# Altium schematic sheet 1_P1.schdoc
size 307 x 218 mm; Symbol: Drawing-Symbol_A4; Device: Drawing-Symbol_A4; Company: 嘉立创EDA; Version: V1.0; Page Size: A4; @Project Name: backscatter; @Page Count: 1; @Update Date: 2026-03-28; @Create Date: 2026-03-27; @Schematic Name: Schematic1; @Page No: 1; @Page Name: P1; @Board Name: Board1; @Create Time: 00:06:39; @Update Time: 16:08:41; Title Block Position: 3; Size: A4; Width: 1170; Height: 825; Region Start: 1; X Region Count: 6; Y Region Count: 4; Blade Width: 10
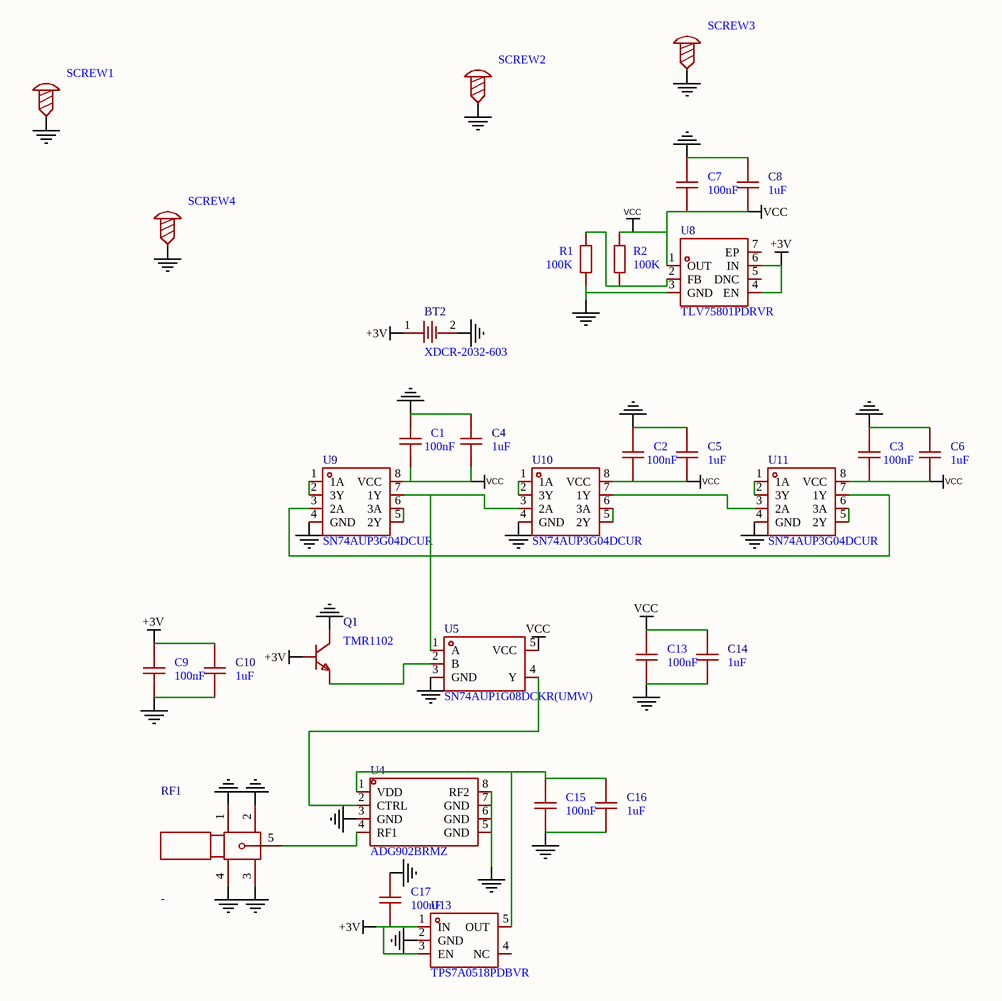
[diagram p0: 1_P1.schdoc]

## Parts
BT2  XDCR-2032-603  [BAT-SMD_XDCR-2032-603]
C1  100nF  [C0603]
C2  100nF  [C0603]
C3  100nF  [C0603]
C4  1uF  [C0603]
C5  1uF  [C0603]
C6  1uF  [C0603]
C7  100nF  [C0603]
C8  1uF  [C0603]
C9  100nF  [C0603]
C10  1uF  [C0603]
C13  100nF  [C0603]
C14  1uF  [C0603]
C15  100nF  [C0603]
C16  1uF  [C0603]
C17  100nF  [C0603]
Q1  TMR1102  [SOT-23-3_L2.9-W1.3-P1.90-LS2.4-BR]
R1  100K  [R0603]
R2  100K  [R0603]
RF1  -  [SMA-SMD_BWSMA-KE-P001]
SCREW1  (no value)  [M3螺丝]
SCREW2  (no value)  [M3螺丝]
SCREW3  (no value)  [M3螺丝]
SCREW4  (no value)  [M3螺丝]
U4  ADG902BRMZ  [MSOP-8_L3.0-W3.0-P0.65-LS5.0-BL]
U5  SN74AUP1G08DCKR(UMW)  [SC-70-5_L2.1-W1.3-P0.65-LS2.2-BR]
U8  TLV75801PDRVR  [WSON-6_L2.0-W2.0-P0.65-TL-EP]
U9  SN74AUP3G04DCUR  [VSSOP-8_L2.3-W2.0-P0.50-LS3.1-BL]
U10  SN74AUP3G04DCUR  [VSSOP-8_L2.3-W2.0-P0.50-LS3.1-BL]
U11  SN74AUP3G04DCUR  [VSSOP-8_L2.3-W2.0-P0.50-LS3.1-BL]
U13  TPS7A0518PDBVR  [SOT-23-5_L3.0-W1.7-P0.95-LS2.8-BR]

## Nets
+3V: BT2.1 C9.2 C10.2 C17.2 Q1.1(B) U8.4(EN) U8.6(IN) U13.1(IN) U13.3(EN)
GND: BT2.2 C1.2 C2.2 C3.2 C4.2 C5.2 C6.2 C7.2 C8.2 C9.1 C10.1 C13.1 C14.1 C15.1 C16.1 C17.1 Q1.3(C) R1.1 RF1.1 RF1.2 RF1.3 RF1.4 SCREW1.1 SCREW2.1 SCREW3.1 SCREW4.1 U4.3(GND) U4.5(GND) U4.6(GND) U4.7(GND) U4.8(RF2) U5.3(GND) U8.3(GND) U9.4(GND) U10.4(GND) U11.4(GND) U13.2(GND)
VCC: C1.1 C2.1 C3.1 C4.1 C5.1 C6.1 C7.1 C8.1 C13.2 C14.2 R2.2 U5.5(VCC) U8.1(OUT) U9.8(VCC) U10.8(VCC) U11.8(VCC)
NetC15_2: C15.2 C16.2 U4.1(VDD) U13.5(OUT)
NetQ1_2: Q1.2(E) U5.2(B)
NetR1_2: R1.2 R2.1 U8.2(FB)
NetRF1_5: RF1.5 U4.4(RF1)
NetU4_2: U4.2(CTRL) U5.4(Y)
NetU5_1: U5.1(A) U9.7(1Y) U10.3(2A)
NetU9_1: U9.1(1A) U9.2(3Y)
NetU9_3: U9.3(2A) U11.7(1Y)
NetU9_5: U9.5(2Y) U9.6(3A)
NetU10_1: U10.1(1A) U10.2(3Y)
NetU10_5: U10.5(2Y) U10.6(3A)
NetU10_7: U10.7(1Y) U11.3(2A)
NetU11_1: U11.1(1A) U11.2(3Y)
NetU11_5: U11.5(2Y) U11.6(3A)

Not connected (* = marked no-connect by the designer): U8 5(DNC) 7(EP); U13 4(NC)

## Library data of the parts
BT2 = XDCR-2032-603: Manufacturer: LX(连欣科技); Add into BOM: yes; Connector Type: 电池底座; Battery Type: CR2032
C1-C3 C7 C9 C13 C15 C17 = CAP_0603: Symbol: CapAcitance; Convert to PCB: yes
C4-C6 C8 C10 C14 C16 = CGA0603X5R105K500JT: Manufacturer: HRE(芯声); Add into BOM: yes; Tolerance: ±10%; Voltage Rating: 50V; Temperature Coefficient: X5R
Q1 = MMBT3904_C7420353: Manufacturer: R+O(宏嘉诚); Add into BOM: yes; type: NPN; Current - Collector(Ic): 200mA; Collector - Emitter Voltage VCEO: 40V; Pd - Power Dissipation: 200mW; DC Current Gain: 100@10mA,1.0V; Transition frequency(fT): 300MHz; Current - Collector Cutoff: 100nA; Vce Saturation(VCE(sat)): 300mV; Emitter-Base Voltage(Vebo): 6V
R1 R2 = Res_0603: Symbol: 电阻; Convert to PCB: yes
RF1 = BWSMA-KE-P001: Manufacturer: BAT WIRELESS(蝙蝠无线); Add into BOM: yes; Connector Type: 板端; Interface: 内孔; Number of Ports: 1; Interface Diameter: 5.2mm; RF Series: SMA; Impedance: 50Ω; Style: 偏脚
SCREW1-SCREW4 = M3螺丝: Symbol: 螺丝孔; Convert to PCB: yes
U4 = ADG902BRMZ: Manufacturer: ADI(亚德诺); Add into BOM: yes; isolation: 40dB; Insertion loss: 0.8dB; Frequency range: 0Hz~2.5GHz; Supply voltage: 1.65V~2.75V
U5 = SN74AUP1G08DCKR(UMW): Manufacturer: UMW(友台半导体); Add into BOM: yes
U8 = TLV75801PDRVR: Manufacturer: TI(德州仪器); Add into BOM: yes; Output Type: 可调; Maximum Input Voltage: 6V; Output Voltage: 550mV~5.5V; Output Current: 500mA; Dropout Voltage: 880mV@(500mA); standby current: 31uA; Output Polarity: 正极; Number of Outputs: 1
U9-U11 = SN74AUP3G04DCUR: Manufacturer: TI(德州仪器); Add into BOM: yes; Voltage - Supply: 800mV~3.6V; Quiescent Current(Iq): 900nA; Number of Circuits: 3; Current - Output Low(IOL): 4mA; Propagation Delay: 3.4ns@3.3V,15pF
U13 = TPS7A0518PDBVR: Manufacturer: TI(德州仪器); Add into BOM: yes; Output Type: 固定; Maximum Input Voltage: 5.5V; Output Voltage: 1.8V; Output Current: 200mA; Dropout Voltage: 382mV@(200mA); standby current: 3uA; Output Polarity: 正极; Number of Outputs: 1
